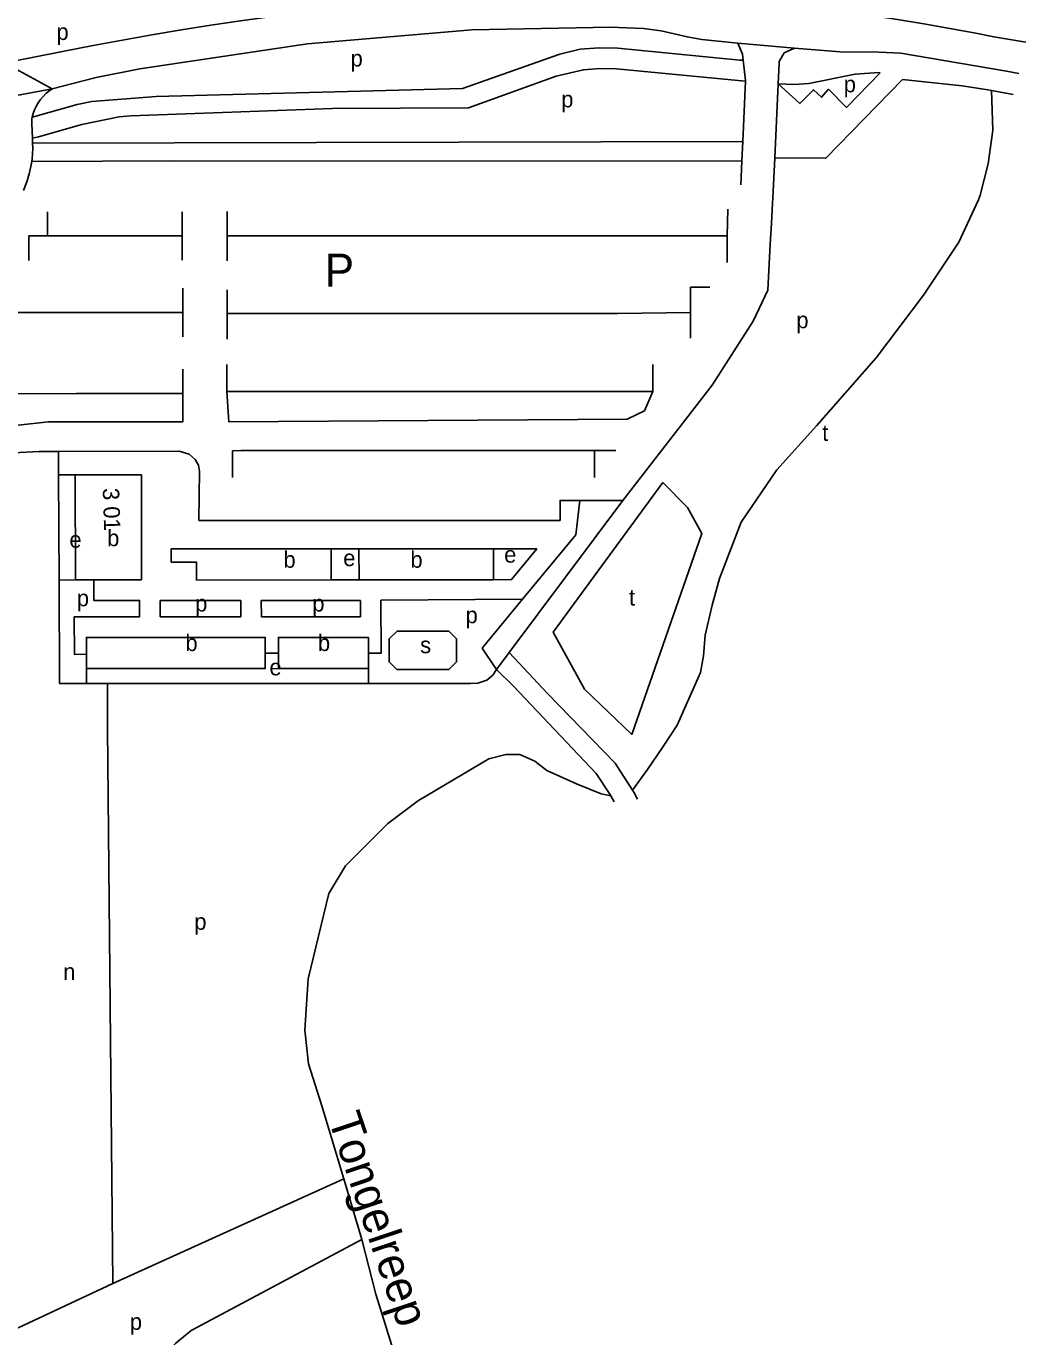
# Model space of a CAD drawing. Extents: x 160204 to 161526, y 379528 to 381793.
# Drawn here: x 161020.2 to 161263.8, y 380595.7 to 380915 of the extents above; entities that cross this region are included whole.
import ezdxf

# ---------------------------------------------------------------- set-up
doc = ezdxf.new("R2010")
doc.units = 0
for name, color, linetype in [('BLT_Basislijn', 7, 'Continuous'), ('BLT_Bebouwing', 7, 'Continuous'), ('BLT_Centroide', 7, 'Continuous'), ('BLT_Huisnummer', 7, 'Continuous'), ('BLT_Tekst_parkeren', 7, 'Continuous'), ('BLT_Vlakafsluiter', 7, 'Continuous'), ('BLT_Waternaam_spoorwegen', 7, 'Continuous')]:
    doc.layers.add(name, color=color, linetype=linetype)

msp = doc.modelspace()

# ---------------------------------------------------------------- linework, layer by layer
at = {"layer": 'BLT_Basislijn'}
for p, q in [((161255.96, 380912.42), (161263.79, 380911.1)), ((161233.3, 380908.45), (161227.98, 380908.72)), ((161203.7, 380906.02), (161203.47, 380901.02)), ((161195.49, 380901.66), (161194.82, 380886.96)), ((161203.47, 380901.02), (161202.64, 380882.92)), ((161254.54, 380899.5), (161255.4, 380899.35)), ((161255.4, 380899.35), (161260.7, 380898.4)), ((161021.62, 380892.88), (161021.52, 380892.44)), ((161021.52, 380892.44), (161021.56, 380891.2)), ((161021.56, 380891.2), (161021.67, 380887.77)), ((161021.67, 380887.77), (161021.71, 380886.56)), ((161021.71, 380886.56), (161194.82, 380886.96)), ((161021.71, 380886.56), (161021.75, 380885.23)), ((161194.82, 380886.96), (161194.6, 380882.13)), ((161202.64, 380882.92), (161202.24, 380874.77)), ((161055.99, 380882.2), (161021.52, 380882.08)), ((161055.99, 380882.2), (161194.6, 380882.13)), ((161194.6, 380882.13), (161194.33, 380876.4)), ((161202, 380870.37), (161202.24, 380874.77)), ((161190.97, 380863.91), (161191.18, 380870.41)), ((161202, 380870.37), (161201.81, 380866.96)), ((161025.33, 380869.83), (161025.33, 380863.91)), ((161058.17, 380869.83), (161058.17, 380863.91)), ((161069.16, 380869.87), (161069.16, 380863.91)), ((161201.81, 380866.96), (161201.52, 380861.9)), ((161058.17, 380863.91), (161020.79, 380863.91)), ((161020.79, 380863.91), (161020.79, 380857.91)), ((161058.17, 380863.91), (161058.17, 380857.99)), ((161164.28, 380863.91), (161069.16, 380863.91)), ((161069.16, 380863.91), (161069.16, 380857.85)), ((161190.97, 380863.91), (161164.28, 380863.91)), ((161190.97, 380863.91), (161190.97, 380857.42)), ((161058.35, 380851.2), (161058.35, 380845.29)), ((161069.16, 380850.82), (161069.16, 380838.81)), ((161182.07, 380851.44), (161182.07, 380845.24)), ((161186.79, 380851.44), (161182.07, 380851.44)), ((161058.35, 380845.29), (161007.77, 380845.29)), ((161058.35, 380845.29), (161058.35, 380839.37)), ((161164.28, 380845.03), (161069.16, 380845.03)), ((161164.28, 380845.03), (161182.07, 380845.24)), ((161182.07, 380845.24), (161182.07, 380839.02)), ((161069.07, 380832.56), (161069.07, 380826.01)), ((161172.9, 380832.56), (161172.9, 380826.01)), ((161058.35, 380831.44), (161058.35, 380825.52)), ((161032.39, 380825.52), (161007.79, 380825.48)), ((161058.35, 380825.52), (161032.39, 380825.52)), ((161172.9, 380826.01), (161069.07, 380826.01)), ((161028.07, 380805.7), (161028.07, 380811.43)), ((161070.43, 380811.59), (161070.43, 380805.05)), ((161158.68, 380811.62), (161158.68, 380805.05)), ((161158.68, 380811.62), (161163.88, 380811.62)), ((161032.13, 380805.7), (161028.07, 380805.7)), ((161028.07, 380805.7), (161028.19, 380780.09)), ((161165.55, 380799.47), (161137.91, 380762.41)), ((161094.47, 380787.7), (161101.27, 380787.7)), ((161032.15, 380780.11), (161028.19, 380780.09)), ((161094.47, 380780.11), (161101.28, 380780.11)), ((161052.81, 380775.09), (161072.47, 380775.1)), ((161052.81, 380771.1), (161052.81, 380775.09)), ((161072.47, 380775.1), (161072.49, 380771.1)), ((161077.47, 380775.1), (161101.62, 380775.12)), ((161077.47, 380775.1), (161077.49, 380771.1)), ((161101.62, 380775.12), (161101.65, 380771.09)), ((161072.49, 380771.1), (161052.81, 380771.1)), ((161101.65, 380771.09), (161077.49, 380771.1)), ((161078.41, 380762.29), (161081.63, 380762.28)), ((161134.8, 380758.31), (161137.91, 380762.41)), ((161034.85, 380758.51), (161034.85, 380754.87)), ((161103.61, 380758.53), (161103.6, 380754.86)), ((161034.85, 380754.87), (161039.98, 380754.87)), ((161039.98, 380754.87), (161040, 380744.01)), ((161039.98, 380754.87), (161103.6, 380754.86)), ((161168.22, 380728.4), (161167.97, 380728.87)), ((161169.12, 380726.69), (161168.22, 380728.4)), ((161097.55, 380634.18), (161041.32, 380608.7)), ((161101.96, 380619.41), (161097.55, 380634.18)), ((161041.32, 380608.7), (161009.91, 380593.97))]:
    msp.add_line(p, q, dxfattribs=at)
for points in [[(161168.26, 380922.68), (161174.71, 380922.43), (161181.17, 380922.11), (161187.61, 380921.7), (161194.05, 380921.22), (161200.49, 380920.66), (161206.91, 380920.01), (161213.33, 380919.29), (161219.74, 380918.49), (161226.14, 380917.6), (161232.53, 380916.64), (161238.9, 380915.6), (161245.27, 380914.48), (161251.61, 380913.29), (161255.96, 380912.42)], [(161036.52, 380910.29), (161043.66, 380911.66), (161050.82, 380912.94), (161057.98, 380914.15), (161065.16, 380915.27), (161072.36, 380916.32), (161079.56, 380917.29), (161086.77, 380918.17), (161093.05, 380918.88)], [(161162.59, 380914.77), (161128.8, 380914.16), (161088.7, 380910.76), (161047.85, 380904.6), (161037.25, 380902.53), (161026.47, 380899.79)], [(161193.61, 380910.89), (161184.8, 380911.82), (161181.24, 380912.4), (161174.89, 380913.9), (161170.62, 380914.47), (161162.59, 380914.77)], [(161014.88, 380906.09), (161017.51, 380906.61), (161033.56, 380909.73), (161036.52, 380910.29)], [(161194.91, 380906.72), (161194.11, 380906.79), (161164.37, 380909.64), (161159.84, 380909.75), (161155.22, 380909.39), (161150.26, 380908.23)], [(161193.61, 380910.89), (161194.74, 380908.2), (161194.91, 380906.72)], [(161207.44, 380909.66), (161204.94, 380908.53), (161203.72, 380906.41), (161203.7, 380906.02)], [(161207.44, 380909.66), (161218.58, 380908.74), (161227.98, 380908.72)], [(161233.3, 380908.45), (161259.12, 380904.07), (161262.13, 380903.54)], [(161150.26, 380908.23), (161126.49, 380899.85), (161051.83, 380897.87), (161036.17, 380896.66)], [(161194.91, 380906.72), (161195.5, 380901.81), (161195.49, 380901.66)], [(161042.82, 380892.93), (161045.69, 380893.16), (161094.81, 380894.99), (161127.98, 380895.11), (161149.33, 380902.88)], [(161195.49, 380901.66), (161193.67, 380901.81), (161164.07, 380904.65), (161159.98, 380904.74), (161155.99, 380904.43), (161149.33, 380902.88)], [(161233.72, 380902.07), (161215.03, 380882.85), (161202.64, 380882.92)], [(161228.32, 380903.69), (161228.01, 380903.71), (161222.22, 380903.34), (161210.88, 380901.04), (161207.23, 380900.85), (161203.47, 380901.02)], [(161203.47, 380901.02), (161208.75, 380896.16), (161212.05, 380899.55), (161214, 380897.73), (161215.71, 380899.66), (161220.08, 380895.22), (161228.32, 380903.69)], [(161254.54, 380899.5), (161248.31, 380900.52), (161233.72, 380902.07)], [(161026.47, 380899.79), (161025.69, 380899.22), (161024.96, 380898.59), (161024.28, 380897.9), (161023.66, 380897.16), (161023.11, 380896.36), (161022.67, 380895.61)], [(161252.63, 380873.88), (161254.58, 380881.47), (161255.76, 380889.68), (161255.4, 380899.35)], [(161036.17, 380896.66), (161032.57, 380895.91), (161021.92, 380892.95), (161021.62, 380892.88)], [(161022.67, 380895.61), (161022.21, 380894.65), (161021.87, 380893.75), (161021.62, 380892.88)], [(161042.82, 380892.93), (161033.75, 380891.05), (161023.14, 380888.1), (161021.67, 380887.77)], [(161021.75, 380885.23), (161021.62, 380882.59), (161021.52, 380882.08)], [(161021.52, 380882.08), (161021.28, 380880.83), (161020.86, 380879.09), (161020.37, 380877.38), (161019.79, 380875.68), (161019.55, 380875.02)], [(161167.97, 380728.87), (161171.6, 380733.91), (161175.44, 380739.55), (161178.8, 380744.73), (161184.52, 380757.53), (161185.23, 380761.6), (161185.64, 380766.64), (161187.34, 380773.94), (161189.15, 380780.46), (161194.46, 380794.21), (161203.15, 380806.95), (161212.77, 380817.69), (161227.36, 380834.25), (161238.83, 380849.46), (161247.43, 380862.41), (161252.28, 380872.74), (161252.63, 380873.88)], [(161201.52, 380861.9), (161200.9, 380850.71), (161197.33, 380843.16), (161187.38, 380827.56), (161165.55, 380799.47)], [(161058.35, 380825.52), (161058.32, 380818.6), (161025.6, 380818.6), (161010.72, 380817), (161003.46, 380815.64), (161000.89, 380816.1), (160999.19, 380816.85), (160997.58, 380818.13), (160996.7, 380819.45)], [(161172.9, 380826.01), (161170.82, 380821.29), (161166.67, 380819.24), (161069.56, 380818.6), (161069.07, 380826.01)], [(161013.45, 380810.74), (161015.46, 380810.99), (161023.36, 380811.42), (161028.07, 380811.43)], [(161028.07, 380811.43), (161057.46, 380811.46), (161059.88, 380810.75), (161061.37, 380809.48), (161062.17, 380808.06), (161062.4, 380806.58), (161062.28, 380794.59), (161150.27, 380794.61), (161150.27, 380799.47), (161165.55, 380799.47)], [(161070.43, 380811.59), (161072.53, 380811.62), (161158.68, 380811.62)], [(161155.07, 380799.49), (161154.12, 380791.06), (161141.16, 380775.39)], [(161134.06, 380780.15), (161138.45, 380780.19), (161144.58, 380787.65), (161134.06, 380787.72)], [(161028.19, 380780.09), (161028.3, 380754.87), (161034.85, 380754.87)], [(161036.62, 380780.11), (161036.62, 380775.11), (161047.81, 380775.12), (161047.81, 380771.12), (161031.89, 380771.1), (161031.9, 380761.99), (161034.85, 380761.98)], [(161103.6, 380762.25), (161106.71, 380762.27), (161106.62, 380775.15), (161141.16, 380775.39)], [(161141.16, 380775.39), (161131.31, 380763.47), (161134.8, 380758.31)], [(161137.91, 380762.41), (161147.23, 380752.42), (161163.7, 380735.5), (161167.97, 380728.87)], [(161103.6, 380754.86), (161128.49, 380754.85), (161130.26, 380754.94), (161132.45, 380755.68), (161133.9, 380756.94), (161134.8, 380758.31)], [(161134.8, 380758.31), (161138.95, 380754.21), (161159.04, 380732.91), (161162.4, 380727.9), (161162.64, 380727.51)], [(161041.32, 380608.7), (161040, 380744.01)], [(161097.55, 380634.18), (161092.22, 380651.99), (161089, 380662.17), (161088.04, 380670.41), (161088.92, 380682.92), (161093.9, 380703.72), (161097.97, 380710.48), (161108.34, 380720.74), (161115.74, 380726.33), (161132.93, 380736.5), (161137.08, 380737.61), (161140.45, 380737.56), (161144.11, 380735.92), (161147.08, 380733.64), (161154.25, 380730.44), (161160.28, 380727.96), (161162.64, 380727.51)], [(161163.5, 380726.08), (161162.64, 380727.51)], [(161101.96, 380619.41), (161060.41, 380597.22), (161056.6, 380594.15), (161054.19, 380591.8), (161050.24, 380585.91), (161048.24, 380580.88), (161047.2, 380574.27), (161047.88, 380562.69), (161051.13, 380531)], [(161109.59, 380592.52), (161105.39, 380606.08), (161101.96, 380619.41)]]:
    msp.add_lwpolyline(points, dxfattribs=at)
for points in [[(161175.36, 380803.88), (161148.59, 380767.39), (161156.26, 380753.47), (161167.74, 380742.47), (161184.83, 380791.4), (161181.3, 380797.74)], [(161108.63, 380765.77), (161110.56, 380767.65), (161123.19, 380767.63), (161125.07, 380765.76), (161125.07, 380760.12), (161123.18, 380758.28), (161110.53, 380758.29), (161108.63, 380760.15)]]:
    msp.add_lwpolyline(points, close=True, dxfattribs=at)
at = {"layer": 'BLT_Bebouwing'}
for p, q in [((161032.15, 380780.11), (161032.13, 380805.7)), ((161094.47, 380787.7), (161094.47, 380780.11)), ((161101.27, 380787.7), (161134.06, 380787.72)), ((161101.28, 380780.11), (161101.27, 380787.7)), ((161134.06, 380787.72), (161134.06, 380780.15)), ((161036.62, 380780.11), (161032.15, 380780.11)), ((161048.28, 380780.11), (161036.62, 380780.11)), ((161134.06, 380780.15), (161101.28, 380780.11)), ((161103.59, 380766.1), (161103.6, 380762.25)), ((161034.85, 380758.51), (161034.85, 380761.98)), ((161103.6, 380762.25), (161103.61, 380758.53))]:
    msp.add_line(p, q, dxfattribs=at)
for points in [[(161032.13, 380805.7), (161048.26, 380805.7), (161048.28, 380780.11)], [(161094.47, 380780.11), (161061.69, 380780.09), (161061.7, 380784.43), (161055.47, 380784.44), (161055.47, 380787.68), (161094.47, 380787.7)], [(161034.85, 380761.98), (161034.85, 380766.11), (161078.41, 380766.1), (161078.41, 380762.29)], [(161081.63, 380762.28), (161081.63, 380766.1), (161103.59, 380766.1)], [(161078.41, 380762.29), (161078.41, 380758.52), (161034.85, 380758.51)], [(161103.61, 380758.53), (161081.63, 380758.52), (161081.63, 380762.28)]]:
    msp.add_lwpolyline(points, dxfattribs=at)
at = {"layer": 'BLT_Vlakafsluiter'}
for p, q in [((161207.44, 380909.66), (161193.61, 380910.89)), ((161014.88, 380906.09), (161026.47, 380899.79)), ((161026.47, 380899.79), (161008.3, 380896.34))]:
    msp.add_line(p, q, dxfattribs=at)

# ---------------------------------------------------------------- texts
at = {"layer": 'BLT_Centroide'}
for s, p in [('p', (161027.54, 380911.67)), ('p', (161099.23, 380905.19)), ('p', (161219.42, 380898.92)), ('p', (161150.56, 380895.25)), ('p', (161207.87, 380841.43)), ('t', (161214.17, 380813.97)), ('e', (161030.7, 380787.95)), ('b', (161039.89, 380788.33)), ('b', (161082.86, 380783.07)), ('b', (161113.81, 380783.07)), ('e', (161136.66, 380784.32)), ('e', (161097.43, 380783.46)), ('t', (161167.08, 380773.87)), ('p', (161032.5, 380773.69)), ('p', (161061.34, 380772.41)), ('p', (161089.9, 380772.41)), ('p', (161127.25, 380769.55)), ('b', (161058.97, 380762.78)), ('b', (161091.27, 380762.78)), ('s', (161116.17, 380762.25)), ('e', (161079.46, 380756.86)), ('p', (161061.14, 380694.85)), ('n', (161029.18, 380682.66)), ('p', (161045.42, 380597.39))]:
    msp.add_text(s, height=4, dxfattribs=at).set_placement(p)
at = {"layer": 'BLT_Huisnummer'}
msp.add_text('3 01', height=4, rotation=272, dxfattribs=at).set_placement((161038.81, 380802.44))
at = {"layer": 'BLT_Tekst_parkeren'}
msp.add_text('P', height=8, dxfattribs=at).set_placement((161092.94, 380851.6))
at = {"layer": 'BLT_Waternaam_spoorwegen'}
msp.add_text('Tongelreep', height=8, rotation=288.582, dxfattribs=at).set_placement((161093.7, 380648.86))

doc.saveas('drawing.dxf')
